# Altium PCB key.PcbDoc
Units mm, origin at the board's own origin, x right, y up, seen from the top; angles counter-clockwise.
Board outline 15.13 x 40.13 mm, 2 copper layers (Top Layer, Bottom Layer); 14 components, 10 nets, 38 pads, 15 vias.
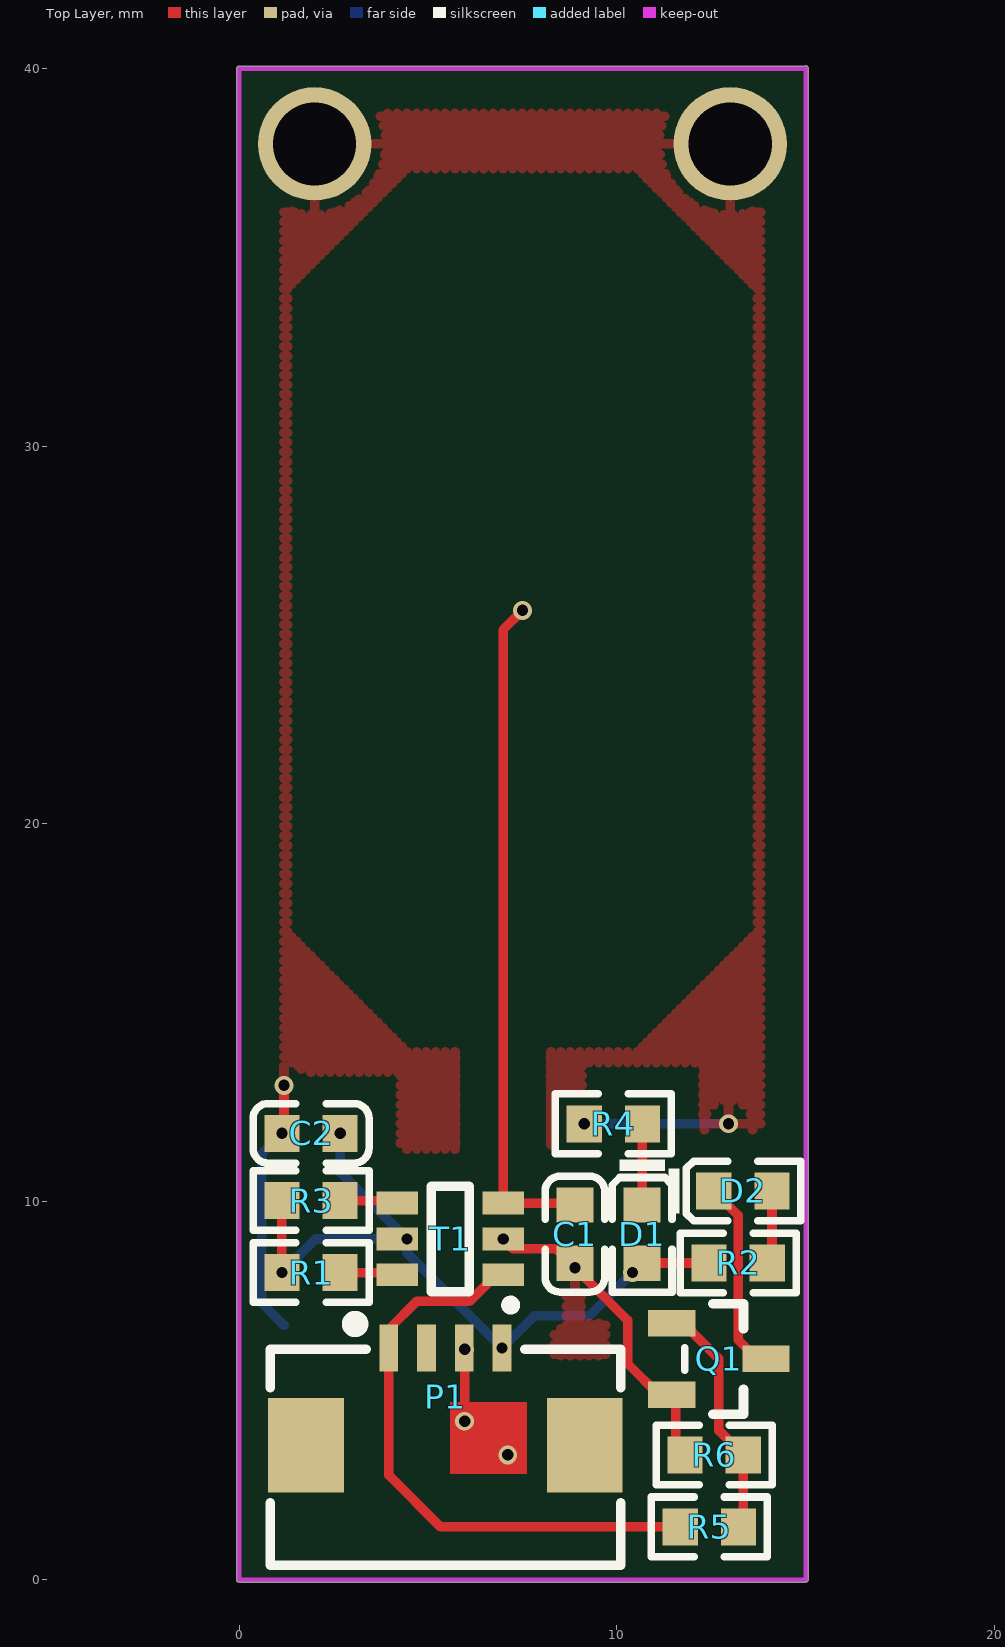
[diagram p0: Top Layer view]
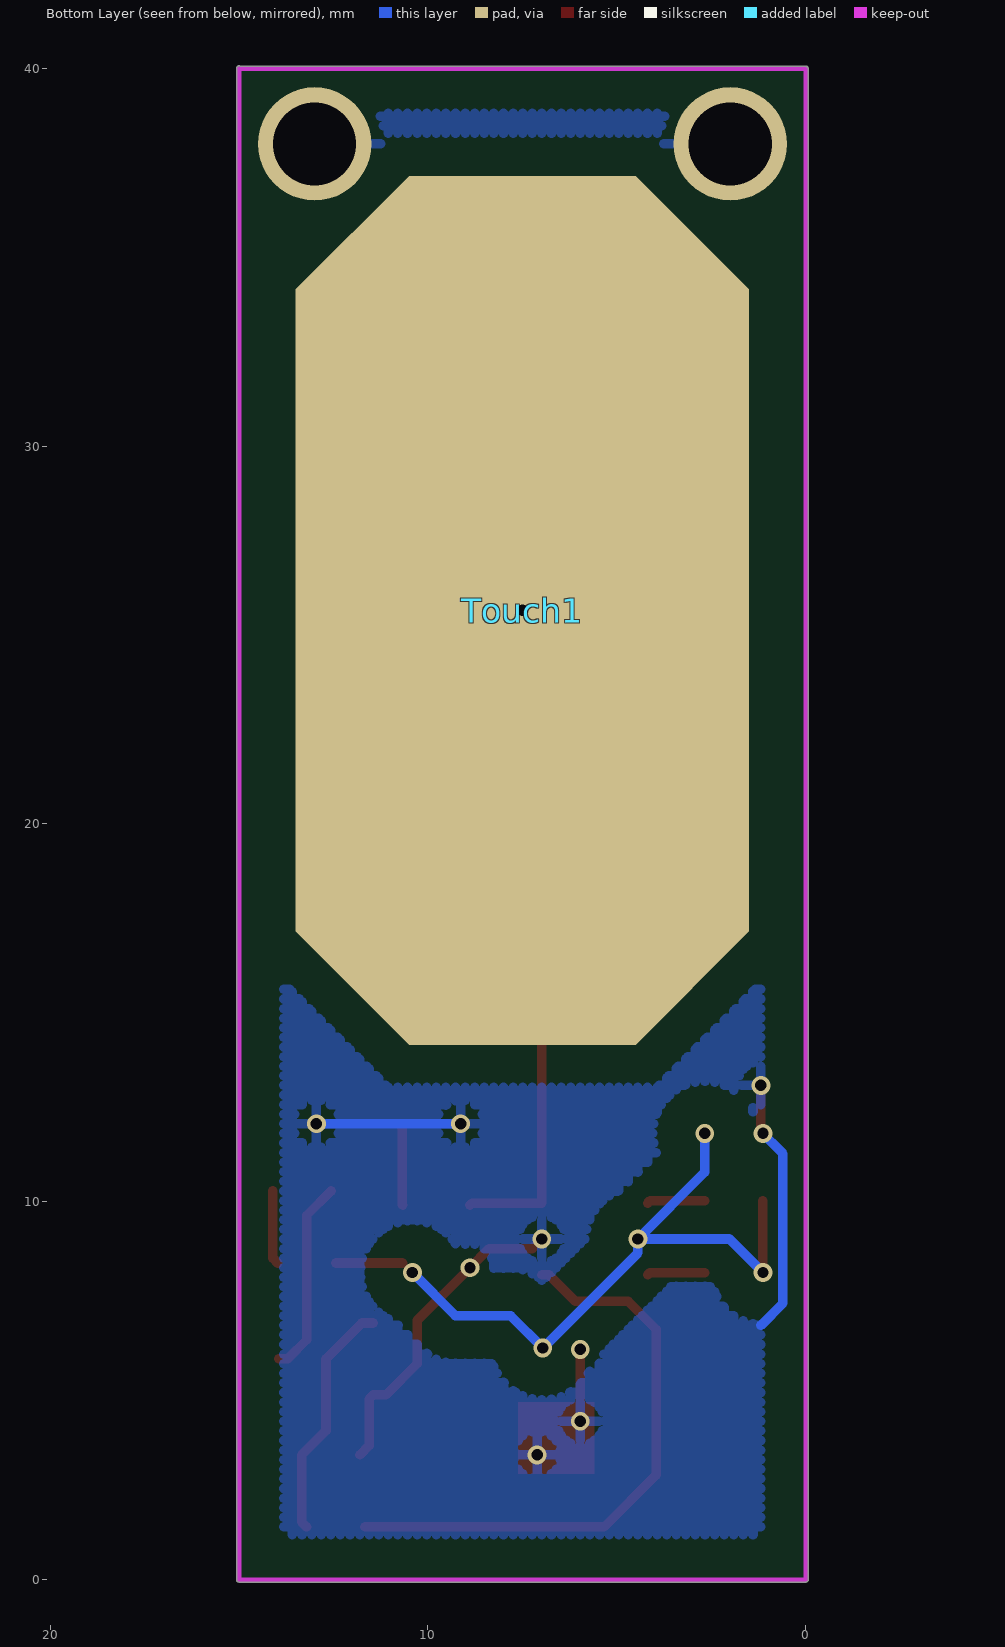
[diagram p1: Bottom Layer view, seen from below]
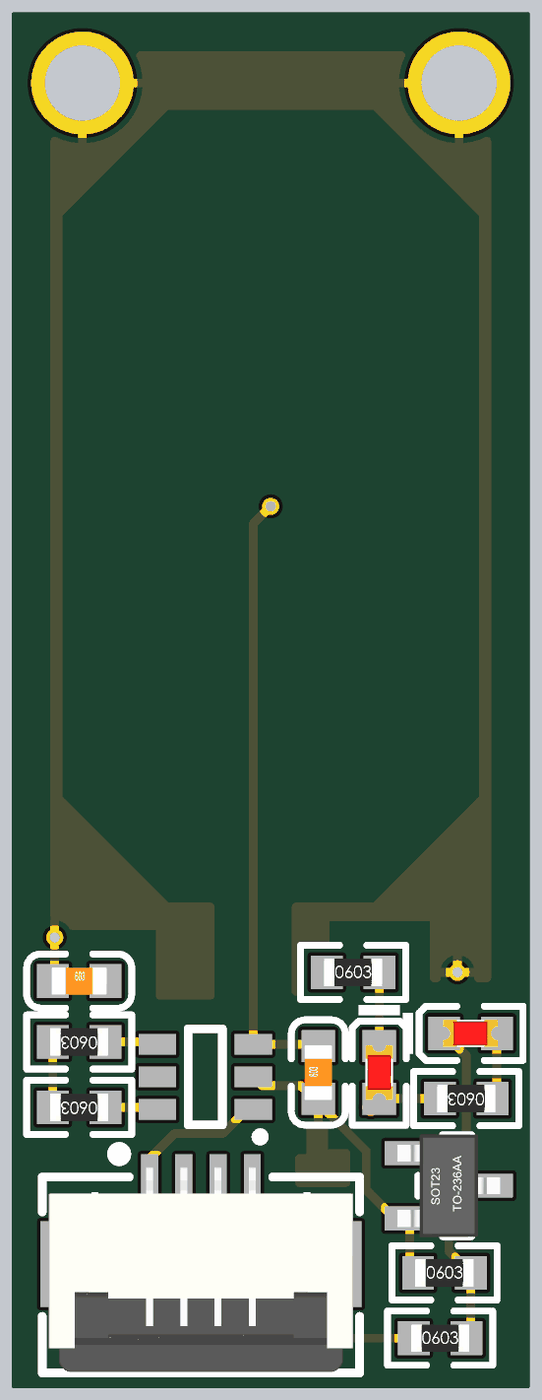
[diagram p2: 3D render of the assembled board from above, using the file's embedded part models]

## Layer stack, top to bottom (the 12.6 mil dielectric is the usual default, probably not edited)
Top Solder: solder mask 0.0102, Solder Resist, Dk 3.5
Top Layer: signal copper 0.0356
Dielectric 1: dielectric 0.32, FR-4, Dk 4.8
Bottom Layer: signal copper 0.0356
Bottom Solder: solder mask 0.0102, Solder Resist, Dk 3.5

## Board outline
-0.064,0 ccw(c0,0) 0,-0.064 15,-0.064 ccw(c15,0) 15.064,0 15.064,40 ccw(c15,40) 14.976,40.059 0,40.059 ccw(c0,39.996) -0.064,39.996

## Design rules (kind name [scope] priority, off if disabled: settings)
Clearance CU [InPolygon] p1: gap=1
Clearance Clearance_1 [All] p2: gap=0.152
PolygonConnect [All] p1: connectstyle=Relief reliefconductorwidth=0.254 reliefentries=4 polygonreliefangle="90 Angle" airgapwidth=0.254
RoutingVias [All] p1: holewidth=0.3 width=0.5 viastyle="Through Hole" minholewidth=0.3 minwidth=0.5 maxholewidth=0.5 maxwidth=1.27
SolderMaskExpansion [All] p1: expansion=0.102
Width [All] p1: maxlimit=0.254 minlimit=0.254 preferedwidth=0.254
30 further rules are at their usual default settings.

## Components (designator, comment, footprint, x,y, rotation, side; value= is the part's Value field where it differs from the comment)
C1 "10pF (100) 5% 50V" 0603_C 8.89,9.144 r90 top
C2 "100nF (104) 10% 50V" 0603_C 1.905,11.811 r0 top
D1 "绿灯 0603" 0603_LED_S1 10.668,9.144 r270 top
D2 "黄灯 0603" 0603_LED_S1 13.335,10.287 r0 top
P1 "Header 4" FPC1.0-2H-WS-4P 5.461,3.556 r0 top
Q1 "SS8050 Y1" SOT-23(SOT-23-3) 12.7,5.842 r180 top
R1 "NC" 0603_R 1.905,8.128 r180 top
R2 "470Ω (4700) ±1%" 0603_R 13.208,8.382 r180 top
R3 "NC" 0603_R 1.905,10.033 r180 top
R4 "470Ω (4700) ±1%" 0603_R 9.906,12.065 r0 top
R5 "1KΩ (1001) ±1%" 0603_R 12.446,1.397 r0 top
R6 "10KΩ (1002) ±1%" 0603_R 12.573,3.302 r0 top
T1 "TTP223" SOT-23-6 5.588,9.017 r0 top
Touch1 "TP" TP 6.985,25.654 r90 bottom

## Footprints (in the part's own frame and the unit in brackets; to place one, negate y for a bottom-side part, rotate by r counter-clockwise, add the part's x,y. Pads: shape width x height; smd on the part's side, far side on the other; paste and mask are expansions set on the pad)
0603_C [mm]
  rect 0.93x0.98 smd: 1(-0.77,0) 2(0.77,0)
  silkscreen extent -1.53,-0.79 1.54,0.79, body extent -0.8,-0.4 0.8,0.4, height 0.3
0603_LED_S1 [mm]
  rect 0.93x0.98 smd: A(0.77,0) K(-0.77,0)
  silkscreen extent -1.98,-0.79 1.54,0.79, body extent -0.8,-0.4 0.8,0.4, height 0.6
0603_R [mm]
  rect 0.93x0.98 smd: 1(-0.77,0) 2(0.77,0)
  silkscreen extent -1.53,-0.79 1.54,0.79, body extent -0.85,-0.4 0.85,0.4, height 0.56
FPC1.0-2H-WS-4P [mm] "翻盖FPC，脚距1mm，不含脚（长8.9mm，宽5.2mm，高1.96mm）"
  rect 2x2.5 smd: 0(-3.69,0) 0(3.69,0)
  rect 0.5x1.25 smd: 1(-1.5,2.575) 2(-0.5,2.575) 3(0.5,2.575) 4(1.5,2.575)
  silkscreen extent -4.64,-3.17 4.64,3.31, body extent -4.45,-3.15 4.45,2.85, height 2
SOT-23(SOT-23-3) [mm]
  rect 1.25x0.7 smd: 1(1.25,-0.95) 2(1.25,0.95) 3(-1.25,0)
  silkscreen extent -0.65,-1.46 0.9,1.46, body extent -1.5,-1.5 1.5,1.5, height 1.3
SOT-23-6 [mm]
  rect 1.1x0.6 smd: 1(1.4,-0.95) 2(1.4,0) 3(1.4,0.95) 4(-1.4,0.95) 5(-1.4,0) 6(-1.4,-0.95)
  silkscreen extent -0.5,-1.87 1.73,1.4
TP [mm]
  oct 23x12 smd mask+0.3: 1(0,0.515)

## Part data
C1: library part "0603 10pF (100) 5% 50V", "贴片电容"
C2: library part "0603 100nF (104) 10% 50V", "贴片电容"
D1: library part "0603 绿灯", "发光二极管"
D2: library part "0603 黄灯", "发光二极管"
P1: "Header, 4-Pin"
Q1: library part "SOT-23 SS8050 Y1", "三极管"
R1 R3 R6: library part "0603 10KΩ (1002) 1%", "贴片电阻"
R2 R4: library part "0603 470Ω (4700) 1%", "贴片电阻"
R5: library part "0603 1KΩ (1001) 1%", "贴片电阻"

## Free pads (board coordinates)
  round 3 hole 2.2: 2(13,38) 3(2,38)

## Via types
v1: diameter 0.5, hole 0.3, Top Layer to Bottom Layer, 15 vias

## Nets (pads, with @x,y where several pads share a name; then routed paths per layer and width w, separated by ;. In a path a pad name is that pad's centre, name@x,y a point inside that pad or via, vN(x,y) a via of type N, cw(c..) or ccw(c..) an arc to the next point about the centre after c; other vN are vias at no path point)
GND: C1.1 C2.1 P1.3 pad.2 pad.3 Q1.2 R4.1 R6.1 T1.2 | length 21.3
  Top Layer w0.254: v1(1.135,11.811) 1.191,11.867 v1(1.191,13.081) ; P1.3 5.961,6.104 v1(5.969,6.096) v1(5.969,4.191) ; v1(6.988,9.017) 7.242,8.763 8.382,8.763 v1(8.89,8.255) 10.287,6.858 10.287,5.715 11.11,4.892 Q1.2 11.557,4.785 11.557,3.548 R6.1
  Bottom Layer w0.254: 1.191,6.731 0.606,7.316 0.606,11.274 v1@1.206,11.874 ; v1(9.136,12.065) v1(12.954,12.065)
  other v1: 7.112,3.302
NetC1_2: C1.2 T1.3 Touch1.1 | length 17.8
  Top Layer w0.254: v1(7.5,25.654) 6.988,25.142 T1.3 8.837,9.967 C1.2
NetD1_K: D1.K R4.2 | length 2.2
  Top Layer w0.254: D1.K 10.676,9.922 R4.2
NetD2_A: D2.A R2.1 | length 2
  Top Layer w0.254: R2.1 14.105,8.509 D2.A
NetD2_K: D2.K Q1.3 | length 5.2
  Top Layer w0.254: D2.K 13.208,9.644 13.208,6.35 13.716,5.842 Q1.3
NetQ1_1: Q1.1 R5.2 R6.2 | length 6.4
  Top Layer w0.254: Q1.1 11.75,6.792 12.7,5.842 12.7,3.945 R6.2 13.343,1.524 R5.2
NetR1_1: R1.1 T1.6 | length 1.5
  Top Layer w0.254: R1.1 4.127,8.128 T1.6
NetR3_1: R3.1 T1.4 | length 1.5
  Top Layer w0.254: R3.1 4.122,10.033 T1.4
OUT: P1.1 R5.1 T1.1 | length 15.8
  Top Layer w0.254: T1.1 6.797,8.067 6.096,7.366 4.699,7.366 3.961,6.628 P1.1 3.961,2.77 5.334,1.397 R5.1
VCC: C2.2 D1.A P1.4 R1.2 R2.2 R3.2 T1.5 | length 19.1
  Top Layer w0.254: v1(1.135,8.128) R3.2 ; D1.A 10.676,8.382 R2.2
  Bottom Layer w0.254: v1(1.135,8.128) 2.024,9.017 v1(4.445,9.017) ; v1(2.675,11.811) 2.675,10.787 v1(4.445,9.017) ; v1(10.414,8.128) 9.271,6.985 7.815,6.985 v1(6.961,6.131) 4.445,8.647 v1(4.445,9.017)
pads on no net: P1.0 P1.2

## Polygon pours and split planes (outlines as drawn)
GND on Top Layer "GND_L01_P000" (hatched 90Degree grid 0 track 0.254, remove dead copper, pour order 0): 15,0 15,39.991 14.995,39.996 0,39.996 0,0
GND on Bottom Layer "GND_L02_P002" (hatched 90Degree grid 0 track 0.254, remove dead copper, pour order 2): 15,0 15,40 0.004,40 0,39.996 0,0

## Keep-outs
Keep-Out Layer:
  lines w0.127: 0,37.719 0,39.996 14.995,39.996 ; 0,37.973 0,0 15,0 15,40

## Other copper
Top Layer:
  rectangle: 5.588,2.794 7.62,4.699
  pour cut-out: 4.445,37.338 1.294,34.187 1.294,17.121 4.445,13.97 10.541,13.97 13.716,17.145 13.716,34.163 10.541,37.338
